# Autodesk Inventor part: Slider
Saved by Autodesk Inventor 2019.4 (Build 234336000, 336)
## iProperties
Created: 2021-08
Part Number: Slider
Material: Generic
Document SubType Name: Modeling
Designer: Administrator
Density: 1 g/cm^3
Appearance: Default
Title: Slider v9
Author: Administrator
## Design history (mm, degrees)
feature "Body1"
body "Solid1"
